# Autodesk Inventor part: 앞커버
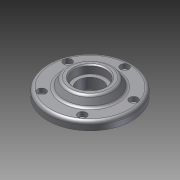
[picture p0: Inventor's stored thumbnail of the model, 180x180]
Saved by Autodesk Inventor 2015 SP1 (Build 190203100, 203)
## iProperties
Company: 한국ATC센터
Created: 2014-03
Part Number: 앞커버
Document SubType Name: Modeling
Designer: KYOUNG IL JANG
Density: 1 g/cm^3
Material: 일반
Appearance: 기본값
Author: KYOUNG IL JANG
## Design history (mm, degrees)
sketch "스케치1"
  geometry: C1 r 26 at (0, 0); C2 r 40 at (0, 0); 1 further point
  constraints: 2 centre point, 2 coincident
  dimensions: "d0" = 52 diameter of C1; "d1" = 80 diameter of C2
extrude "돌출1" new body sketch "스케치1" distance "d2" = 8; taper "d3" = 0 deg
extrude "돌출2" join sketch "스케치1" distance "d4" = 5; taper "d5" = 0 deg
sketch "스케치2"
  geometry: C1 r 25 at (0, 0); 1 further point
  constraints: 1 centre point, 1 coincident
  dimensions: "d6" = 50 diameter of C1
extrude "돌출3" join sketch "스케치2" distance "d7" = 8; taper "d8" = -30 deg
sketch "스케치3"
  geometry: C1 r 1.729 at (0, 33) reference; 1 further point
hole "구멍1" sketch "스케치3" at (0, 33) diameter "d9" = 4.5; stored, may be unused: countersink angle "d13" = 90 deg, drill point angle "d15" = 118 deg; dims "d10" = 6, "d11" = 8, "d12" = 4.4, "d14" = 8
hole "구멍2" diameter "d21" = 23; stored, may be unused: countersink angle "d25" = 90 deg, drill point angle "d27" = 118 deg; dims "d19" = 10, "d20" = 10, "d22" = 6, "d23" = 30, "d24" = 8, "d26" = 8
fillet "모깎기1" dims "d28" = 3, "d29" = 0.3
hole "구멍3" diameter "d32" = 40; stored, may be unused: countersink angle "d36" = 90 deg, drill point angle "d38" = 0 deg; dims "d30" = 10, "d31" = 10, "d33" = 6, "d34" = 30, "d35" = 8, "d37" = 3
fillet "모깎기2" dims "d39" = 3
chamfer "모따기1" distance "d40" = 1; stored, may be unused: second distance "d41" = 2, angle "d42" = 45 deg
node "솔리드1"
pattern_circular "원형 패턴1" dims angle "d17" = 360 deg
node "참조1"
